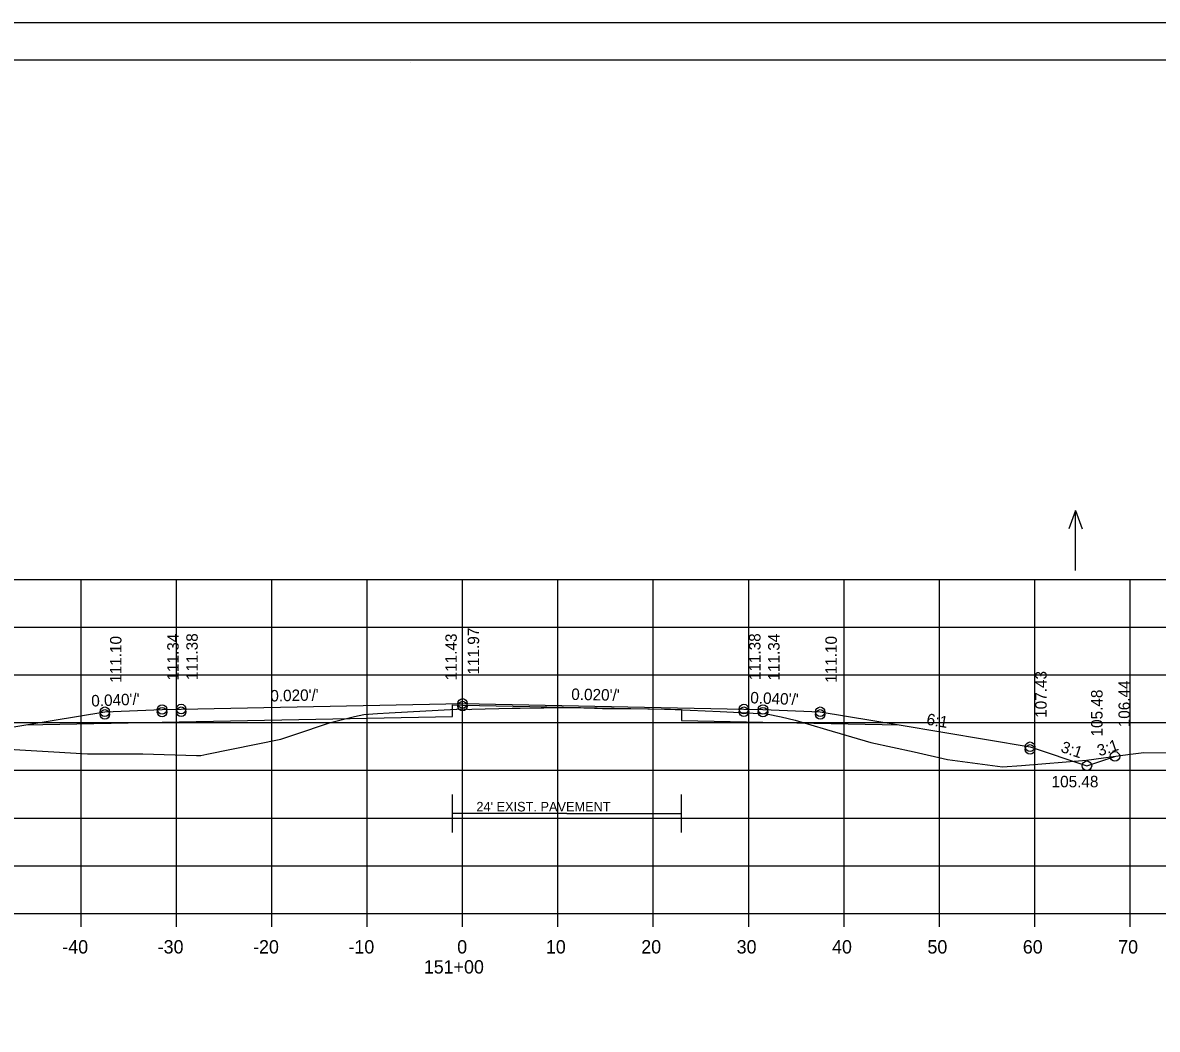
# Model space of a CAD drawing. Extents: x 1175611 to 1176402, y -433344 to -416213.
# Drawn here: x 1175734.9 to 1175853.8, y -429182.3 to -429076.8 of the extents above; entities that cross this region are included whole.
import ezdxf

# ---------------------------------------------------------------- set-up
doc = ezdxf.new("R2010")
doc.units = 0
for name, color, linetype in [('R_Alt Surface', 7, 'Continuous'), ('R_Axis', 7, 'Continuous'), ('R_Axis Annot', 7, 'Continuous'), ('R_Border', 7, 'Continuous'), ('R_Draft', 7, 'Continuous'), ('R_Exist Surface', 7, 'Continuous'), ('R_Fin Surface', 7, 'Continuous'), ('R_Grid', 7, 'Continuous'), ('R_No Plot', 7, 'Continuous'), ('R_Water Annot', 7, 'Continuous'), ('R_Xsect Elev', 7, 'Continuous'), ('R_Xsect Slope', 7, 'Continuous')]:
    doc.layers.add(name, color=color, linetype=linetype)

msp = doc.modelspace()

# ---------------------------------------------------------------- linework, layer by layer
at = {"layer": 'R_Alt Surface'}
msp.add_lwpolyline([(1175735.2, -429150.37), (1175749.47, -429150.09), (1175779.91, -429149.48), (1175779.91, -429148.27), (1175780.97, -429148.29), (1175803.91, -429148.75), (1175803.91, -429149.91), (1175812.47, -429150.09), (1175826.75, -429150.37)], dxfattribs=at)
at = {"layer": 'R_Axis'}
for p, q in [((1175640.97, -429170.13), (1175920.97, -429170.13)), ((1175740.97, -429171.53), (1175740.97, -429170.13)), ((1175750.97, -429171.53), (1175750.97, -429170.13)), ((1175760.97, -429171.53), (1175760.97, -429170.13)), ((1175770.97, -429171.53), (1175770.97, -429170.13)), ((1175780.97, -429171.53), (1175780.97, -429170.13)), ((1175790.97, -429171.53), (1175790.97, -429170.13)), ((1175800.97, -429171.53), (1175800.97, -429170.13)), ((1175810.97, -429171.53), (1175810.97, -429170.13)), ((1175820.97, -429171.53), (1175820.97, -429170.13)), ((1175830.97, -429171.53), (1175830.97, -429170.13)), ((1175840.97, -429171.53), (1175840.97, -429170.13)), ((1175850.97, -429171.53), (1175850.97, -429170.13))]:
    msp.add_line(p, q, dxfattribs=at)
at = {"layer": 'R_Border'}
for p, q in [((1175622.97, -429080.67), (1175939.15, -429080.67)), ((1175775.49, -429080.93), (1175775.49, -429080.93)), ((1175775.49, -429080.93), (1175775.49, -429080.93))]:
    msp.add_line(p, q, dxfattribs=at)
at = {"layer": 'R_Draft'}
for q in [(1175779.91, -429159.66), (1175803.91, -429159.66)]:
    msp.add_line((1175791.91, -429159.66), q, dxfattribs=at)
for points in [[(1175779.91, -429161.66), (1175779.91, -429157.66)], [(1175803.91, -429161.66), (1175803.91, -429157.66)]]:
    msp.add_lwpolyline(points, dxfattribs=at)
at = {"layer": 'R_Exist Surface'}
msp.add_lwpolyline([(1175731.57, -429152.8), (1175741.65, -429153.41), (1175744.16, -429153.41), (1175747.46, -429153.41), (1175753.08, -429153.58), (1175753.55, -429153.59), (1175754.17, -429153.45), (1175761.93, -429151.85), (1175763.3, -429151.4), (1175767.13, -429150.12), (1175769.63, -429149.5), (1175770.63, -429149.27), (1175772.04, -429149.19), (1175773.27, -429149.12), (1175780.35, -429148.71), (1175780.37, -429148.71), (1175780.48, -429148.7), (1175781.49, -429148.73), (1175781.71, -429148.74), (1175781.95, -429148.73), (1175786.19, -429148.63), (1175786.65, -429148.62), (1175787.01, -429148.62), (1175789.22, -429148.59), (1175789.49, -429148.58), (1175790.68, -429148.54), (1175790.86, -429148.54), (1175791.91, -429148.55), (1175792.18, -429148.56), (1175793.68, -429148.58), (1175793.95, -429148.59), (1175795.65, -429148.64), (1175795.98, -429148.64), (1175797.85, -429148.65), (1175798.54, -429148.66), (1175802.62, -429148.73), (1175802.76, -429148.73), (1175803.28, -429148.75), (1175807.99, -429148.97), (1175812.83, -429149.21), (1175814.38, -429149.53), (1175815.83, -429149.89), (1175819.12, -429150.86), (1175823.77, -429152.2), (1175828.32, -429153.2), (1175831.81, -429153.99), (1175835.5, -429154.5), (1175837.57, -429154.78), (1175839.57, -429154.61), (1175846.37, -429154.06), (1175850.73, -429153.49), (1175852.41, -429153.27), (1175859.52, -429153.29)], dxfattribs=at)
at = {"layer": 'R_Fin Surface'}
msp.add_lwpolyline([(1175721.14, -429152.77), (1175721.47, -429152.66), (1175735.2, -429150.37), (1175743.47, -429148.99), (1175749.47, -429148.75), (1175751.47, -429148.71), (1175780.97, -429148.12), (1175810.47, -429148.71), (1175812.47, -429148.75), (1175818.47, -429148.99), (1175826.75, -429150.37), (1175840.47, -429152.66), (1175846.43, -429154.65), (1175849.37, -429153.67)], dxfattribs=at)
msp.add_lwpolyline([(1175721.14, -429152.77), (1175721.47, -429152.66), (1175735.2, -429150.37), (1175743.47, -429148.99), (1175749.47, -429148.75), (1175751.47, -429148.71), (1175780.97, -429148.12), (1175810.47, -429148.71), (1175812.47, -429148.75), (1175818.47, -429148.99), (1175826.75, -429150.37), (1175840.47, -429152.66), (1175846.43, -429154.65), (1175849.37, -429153.67)], dxfattribs=at)
at = {"layer": 'R_Grid'}
for p, q in [((1175640.97, -429135.13), (1175920.97, -429135.13)), ((1175740.97, -429170.13), (1175740.97, -429135.13)), ((1175750.97, -429170.13), (1175750.97, -429135.13)), ((1175760.97, -429170.13), (1175760.97, -429135.13)), ((1175770.97, -429170.13), (1175770.97, -429135.13)), ((1175780.97, -429170.13), (1175780.97, -429135.13)), ((1175790.97, -429170.13), (1175790.97, -429135.13)), ((1175800.97, -429170.13), (1175800.97, -429135.13)), ((1175810.97, -429170.13), (1175810.97, -429135.13)), ((1175820.97, -429170.13), (1175820.97, -429135.13)), ((1175830.97, -429170.13), (1175830.97, -429135.13)), ((1175840.97, -429170.13), (1175840.97, -429135.13)), ((1175850.97, -429170.13), (1175850.97, -429135.13)), ((1175640.97, -429140.13), (1175920.97, -429140.13)), ((1175640.97, -429145.13), (1175920.97, -429145.13)), ((1175640.97, -429150.13), (1175920.97, -429150.13)), ((1175640.97, -429155.13), (1175920.97, -429155.13)), ((1175640.97, -429160.13), (1175920.97, -429160.13)), ((1175640.97, -429165.13), (1175920.97, -429165.13)), ((1175640.97, -429170.13), (1175920.97, -429170.13))]:
    msp.add_line(p, q, dxfattribs=at)
at = {"layer": 'R_No Plot'}
msp.add_line((1175610.57, -429076.77), (1175943.91, -429076.77), dxfattribs=at)
msp.add_lwpolyline([(1175610.57, -429076.77), (1175943.91, -429076.77), (1175943.91, -429290.11), (1175610.57, -429290.11)], close=True, dxfattribs=at)
for centre in [(1175780.97, -429148.12), (1175743.47, -429148.99), (1175743.47, -429149.27), (1175749.47, -429148.75), (1175749.47, -429149.03), (1175751.47, -429148.71), (1175751.47, -429148.99), (1175780.97, -429148.4), (1175810.47, -429148.71), (1175810.47, -429148.99), (1175812.47, -429148.75), (1175812.47, -429149.03), (1175818.47, -429148.99), (1175818.47, -429149.27), (1175840.47, -429152.66), (1175840.47, -429152.94), (1175849.37, -429153.67), (1175849.37, -429153.67), (1175846.43, -429154.65), (1175846.43, -429154.65)]:
    msp.add_circle(centre, 0.5, dxfattribs=at)
at = {"layer": 'R_Water Annot'}
for p, q in [((1175845.24, -429127.9), (1175844.54, -429129.82)), ((1175845.24, -429134.19), (1175845.24, -429127.9)), ((1175845.24, -429127.9), (1175845.94, -429129.82))]:
    msp.add_line(p, q, dxfattribs=at)

# ---------------------------------------------------------------- texts
at = {"layer": 'R_Axis Annot'}
for s, p in [('-40', (1175739.01, -429174.33)), ('-30', (1175749.01, -429174.33)), ('-20', (1175759.01, -429174.33)), ('-10', (1175769.01, -429174.33)), ('0', (1175780.41, -429174.33)), ('10', (1175789.71, -429174.33)), ('20', (1175799.71, -429174.33)), ('30', (1175809.71, -429174.33)), ('40', (1175819.71, -429174.33)), ('50', (1175829.71, -429174.33)), ('60', (1175839.71, -429174.33)), ('70', (1175849.71, -429174.33)), ('151+00', (1175776.91, -429176.43))]:
    msp.add_text(s, height=1.4, dxfattribs=at).set_placement(p)
at = {"layer": 'R_Draft'}
msp.add_text("24' EXIST. PAVEMENT", height=1, dxfattribs=at).set_placement((1175782.42, -429159.44))
at = {"layer": 'R_Xsect Elev'}
for s, p in [('111.97', (1175782.71, -429145.09)), ('111.10', (1175745.21, -429145.96)), ('111.34', (1175751.21, -429145.72)), ('111.38', (1175753.21, -429145.68)), ('111.43', (1175780.37, -429145.7)), ('111.38', (1175812.21, -429145.68)), ('111.34', (1175814.21, -429145.72)), ('111.10', (1175820.21, -429145.96)), ('107.43', (1175842.21, -429149.63)), ('106.44', (1175850.94, -429150.62)), ('105.48', (1175848.07, -429151.58))]:
    msp.add_text(s, height=1.2, rotation=90, dxfattribs=at).set_placement(p)
msp.add_text('105.48', height=1.2, dxfattribs=at).set_placement((1175842.73, -429156.91))
at = {"layer": 'R_Xsect Slope'}
for s, rotation, p in [("0.020'/'", 1.1458, (1175760.83, -429147.92)), ("0.020'/'", 358.8542, (1175792.36, -429147.75)), ("0.040'/'", 2.2906, (1175742.07, -429148.45)), ("0.040'/'", 357.7094, (1175811.12, -429148.1)), ('6:1', 350.5377, (1175829.55, -429150.33)), ('3:1', 341.5651, (1175843.61, -429153.18)), ('3:1', 18.4349, (1175847.74, -429153.68))]:
    msp.add_text(s, height=1.2, rotation=rotation, dxfattribs=at).set_placement(p)

doc.saveas('drawing.dxf')
